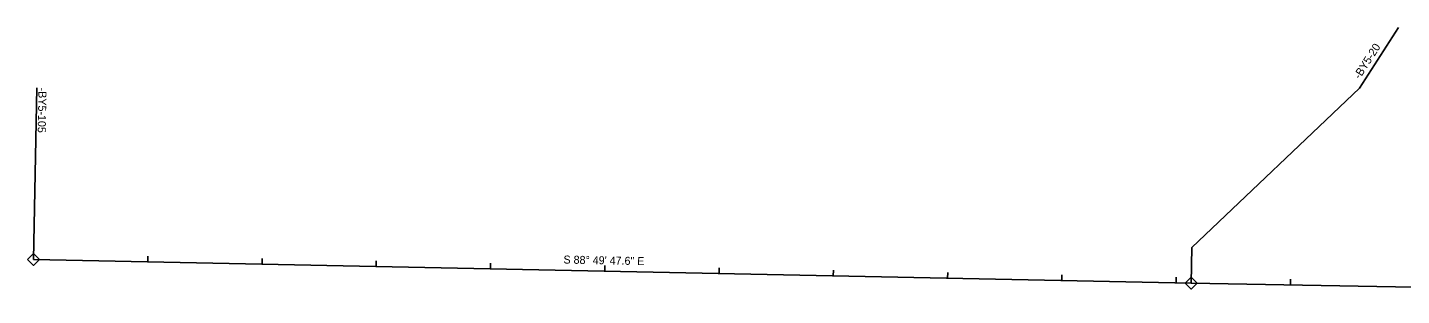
# Model space of a CAD drawing. Extents: x 1975258 to 1978652, y 778250 to 783549.
# Drawn here: x 1975804 to 1977006, y 780866 to 781100 of the extents above; entities that cross this region are included whole.
import ezdxf

# ---------------------------------------------------------------- set-up
doc = ezdxf.new("R2010")
doc.units = 0
for name, color, linetype in [('Prop Drainage Structure Drop Inlet Grate 2 Narrow Slots and Flat Grates 840 29 Label', 7, 'Continuous'), ('Prop Drainage Structure Drop Inlet Grate 2 Narrow Slots and Sag Grates 840 24 CELL', 7, 'Continuous'), ('Prop SS Transition Line', 7, 'Continuous'), ('Sheet Data Field CELL', 7, 'Continuous'), ('Sheet Typical CELL', 7, 'Continuous')]:
    doc.layers.add(name, color=color, linetype=linetype)

msp = doc.modelspace()

# ---------------------------------------------------------------- linework, layer by layer
at = {"layer": 'Prop Drainage Structure Drop Inlet Grate 2 Narrow Slots and Sag Grates 840 24 CELL'}
for p, q in [((1977003.4, 781099.8), (1976969.3, 781046.7)), ((1975809.2, 780897), (1975812.3, 781047)), ((1976822.7, 780907.4), (1976969.3, 781046.7)), ((1976822.7, 780907.4), (1976822.1, 780876.2))]:
    msp.add_line(p, q, dxfattribs=at)
at = {"layer": 'Prop SS Transition Line'}
for p, q in [((1975809.2, 780897), (1975809.2, 780897)), ((1976822.2, 780876.3), (1976822.2, 780876.3))]:
    msp.add_line(p, q, dxfattribs=at)
for points in [[(1975804, 780897), (1975809.2, 780902.3), (1975814.5, 780897), (1975809.2, 780891.8)], [(1976817, 780876.3), (1976822.2, 780881.6), (1976827.5, 780876.3), (1976822.2, 780871.1)]]:
    msp.add_lwpolyline(points, close=True, dxfattribs=at)
at = {"layer": 'Sheet Data Field CELL'}
for p, q in [((1975809.2, 780897), (1975809.3, 780902)), ((1975909.2, 780895), (1975909.3, 780900)), ((1976009.2, 780892.9), (1976009.3, 780897.9)), ((1976109.1, 780890.9), (1976109.2, 780895.9)), ((1976209.1, 780888.8), (1976209.2, 780893.8)), ((1976309.1, 780886.8), (1976309.2, 780891.8)), ((1976409.1, 780884.8), (1976409.2, 780889.8)), ((1976509, 780882.7), (1976509.1, 780887.7)), ((1976609, 780880.7), (1976609.1, 780885.7)), ((1976709, 780878.6), (1976709.1, 780883.6)), ((1976809, 780876.6), (1976809.1, 780881.6)), ((1976909, 780874.8), (1976909.1, 780879.8))]:
    msp.add_line(p, q, dxfattribs=at)
at = {"layer": 'Sheet Typical CELL'}
for p, q in [((1975809.2, 780897), (1976822.2, 780876.3)), ((1976822.2, 780876.3), (1977437.3, 780865.6))]:
    msp.add_line(p, q, dxfattribs=at)

# ---------------------------------------------------------------- texts
at = {"layer": 'Prop Drainage Structure Drop Inlet Grate 2 Narrow Slots and Flat Grates 840 29 Label'}
msp.add_text('S 88%%d 49\' 47.6" E', height=7, rotation=358.8299, dxfattribs=at).set_placement((1976272.9, 780893.5))
at = {"layer": 'Prop Drainage Structure Drop Inlet Grate 2 Narrow Slots and Sag Grates 840 24 CELL'}
for s, rotation, p in [('-BY5-20 ', 57.255, (1976969.6, 781054.1)), ('-BY5-105 ', 268.8299, (1975813.7, 781047.3))]:
    msp.add_text(s, height=7, rotation=rotation, dxfattribs=at).set_placement(p)

doc.saveas('drawing.dxf')
